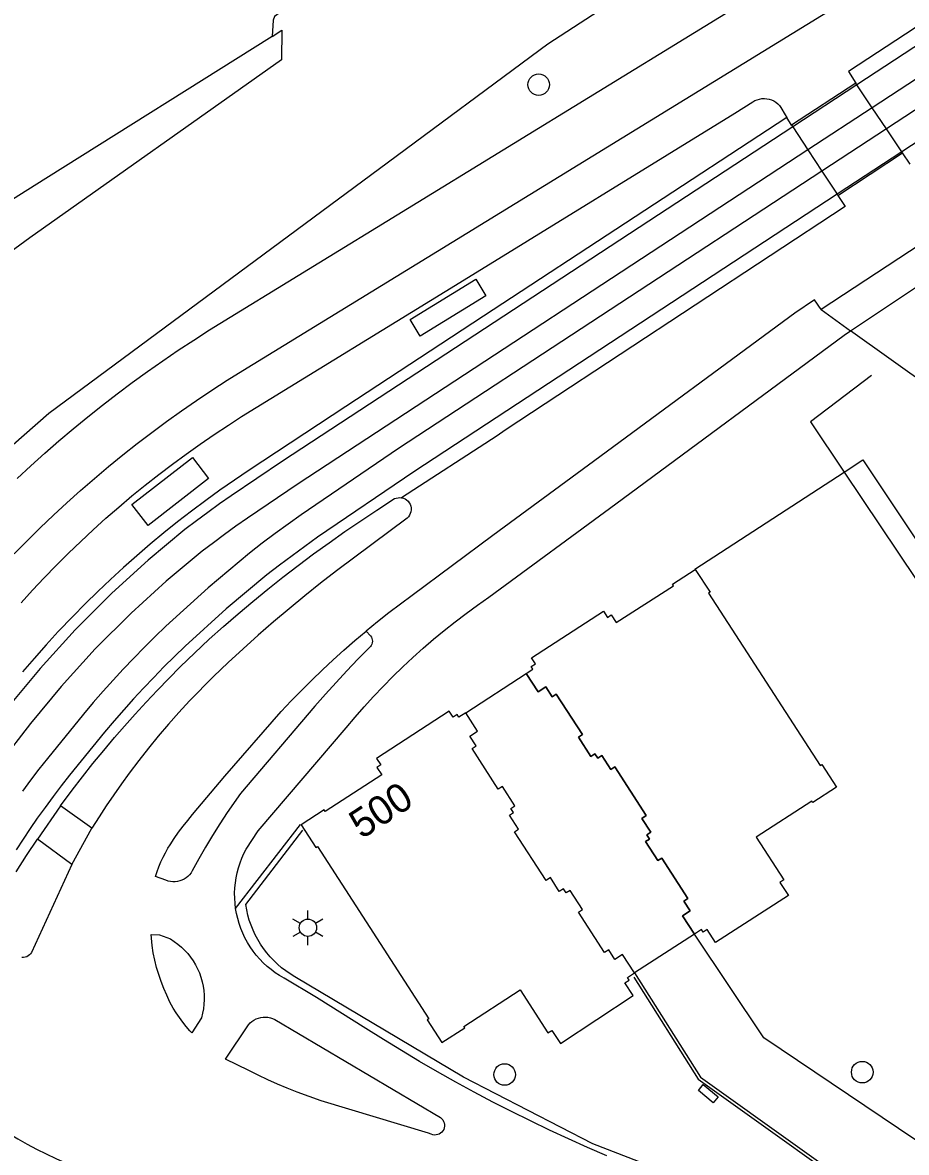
# Model space of a CAD drawing. Extents: x 122462 to 123306, y 485548 to 486417.
# Drawn here: x 123112.8 to 123158.7, y 486289.8 to 486348.4 of the extents above; entities that cross this region are included whole.
import ezdxf

# ---------------------------------------------------------------- set-up
doc = ezdxf.new("R2010")
doc.units = 0
for name, color, linetype in [('Level 1', 7, 'Continuous'), ('Level 10', 7, 'Continuous'), ('Level 16', 7, 'Continuous'), ('Level 17', 7, 'Continuous'), ('Level 19', 7, 'Continuous'), ('Level 2', 7, 'Continuous'), ('Level 20', 7, 'Continuous'), ('Level 24', 7, 'Continuous'), ('Level 25', 7, 'Continuous'), ('Level 37', 7, 'Continuous'), ('Level 40', 7, 'Continuous'), ('Level 44', 7, 'Continuous'), ('Level 50', 7, 'Continuous'), ('Level 53', 7, 'Continuous'), ('Level 58', 7, 'Continuous')]:
    doc.layers.add(name, color=color, linetype=linetype)

msp = doc.modelspace()

# ---------------------------------------------------------------- linework, layer by layer
at = {"layer": 'Level 1'}
for points in [[(123144.558, 486299.075), (123143.943, 486300.024), (123143.549, 486299.768), (123143.222, 486300.271), (123143.012, 486300.134), (123141.653, 486302.233), (123141.859, 486302.367), (123141.216, 486303.356), (123141.012, 486303.224), (123140.87, 486303.443), (123140.659, 486303.306), (123140.195, 486304.019), (123139.968, 486303.872), (123138.332, 486306.399), (123138.541, 486306.535), (123138.073, 486307.256), (123138.282, 486307.392), (123138.14, 486307.61), (123138.349, 486307.745), (123137.702, 486308.745), (123137.492, 486308.609), (123136.128, 486310.716), (123136.339, 486310.852), (123136.008, 486311.364), (123136.41, 486311.624), (123135.798, 486312.574), (123135.445, 486312.346), (123135.358, 486312.48), (123135.148, 486312.344), (123134.946, 486312.655), (123131.169, 486310.21), (123131.388, 486309.873), (123131.187, 486309.743), (123131.441, 486309.353), (123128.503, 486307.452), (123128.449, 486307.536), (123127.25, 486306.76)], [(123127.25, 486306.76), (123128.016, 486305.577), (123128.1, 486305.631), (123133.882, 486296.692), (123133.8, 486296.639), (123134.566, 486295.455), (123135.749, 486296.219), (123135.697, 486296.299), (123138.625, 486298.193), (123140.07, 486295.959), (123140.277, 486296.094), (123140.719, 486295.41), (123144.499, 486297.9), (123144.068, 486298.566), (123144.283, 486298.706), (123144.195, 486298.84), (123144.558, 486299.075)]]:
    msp.add_lwpolyline(points, dxfattribs=at)
at = {"layer": 'Level 10'}
msp.add_lwpolyline([(123144.558, 486299.075), (123143.943, 486300.024), (123143.549, 486299.768), (123143.222, 486300.271), (123143.012, 486300.134), (123141.653, 486302.233), (123141.859, 486302.367), (123141.216, 486303.356), (123141.012, 486303.224), (123140.87, 486303.443), (123140.659, 486303.306), (123140.195, 486304.019), (123139.968, 486303.872), (123138.332, 486306.399), (123138.541, 486306.535), (123138.073, 486307.256), (123138.282, 486307.392), (123138.14, 486307.61), (123138.349, 486307.745), (123137.702, 486308.745), (123137.492, 486308.609), (123136.128, 486310.716), (123136.339, 486310.852), (123136.008, 486311.364), (123136.41, 486311.624), (123135.798, 486312.574), (123138.94, 486314.608), (123139.556, 486313.66), (123139.958, 486313.921), (123140.289, 486313.409), (123140.5, 486313.546), (123141.864, 486311.439), (123141.654, 486311.303), (123142.301, 486310.304), (123142.51, 486310.439), (123142.651, 486310.22), (123142.86, 486310.355), (123143.327, 486309.633), (123143.536, 486309.768), (123145.172, 486307.241), (123144.945, 486307.094), (123145.406, 486306.379), (123145.195, 486306.243), (123145.336, 486306.024), (123145.132, 486305.892), (123145.772, 486304.9), (123145.978, 486305.033), (123147.337, 486302.934), (123147.126, 486302.798), (123147.451, 486302.294), (123147.056, 486302.039), (123147.67, 486301.09), (123144.558, 486299.075)], dxfattribs=at)
at = {"layer": 'Level 16'}
for points in [[(123217.361, 486416.958), (123206.829, 486406.748), (123179.003, 486385.844), (123152.655, 486367.889), (123137.927, 486357.79), (123128.826, 486350.852), (123125.877, 486348.714), (123125.807, 486348.517), (123125.744, 486347.678)], [(123125.744, 486347.678), (123114.003, 486340.298), (123094.86, 486328.266)]]:
    msp.add_lwpolyline(points, dxfattribs=at)
at = {"layer": 'Level 17'}
for p, q in [((123156.044, 486345.251), (123152.716, 486343.072)), ((123156.102, 486345.165), (123156.044, 486345.251)), ((123156.905, 486343.969), (123156.102, 486345.165)), ((123157.637, 486342.879), (123156.905, 486343.969)), ((123152.716, 486343.072), (123152.472, 486343.461)), ((123152.716, 486343.072), (123152.773, 486342.985)), ((123152.773, 486342.985), (123153.567, 486341.783)), ((123168.085, 486342.615), (123154.252, 486333.498)), ((123158.44, 486341.683), (123157.637, 486342.879)), ((123153.567, 486341.783), (123154.291, 486340.687)), ((123155.123, 486339.427), (123158.471, 486341.637)), ((123158.471, 486341.637), (123158.44, 486341.683)), ((123154.291, 486340.687), (123155.085, 486339.485)), ((123155.085, 486339.485), (123155.123, 486339.427)), ((123154.252, 486333.498), (123155.775, 486332.404)), ((123160.559, 486328.969), (123155.775, 486332.404)), ((123114.765, 486307.744), (123113.564, 486306.012)), ((123116.4, 486306.588), (123114.765, 486307.744)), ((123115.361, 486304.695), (123116.4, 486306.588)), ((123115.361, 486304.695), (123113.564, 486306.012))]:
    msp.add_line(p, q, dxfattribs=at)
for points in [[(123112.519, 486324.734), (123113.232, 486325.395), (123113.954, 486326.046), (123114.686, 486326.685), (123115.428, 486327.313), (123116.179, 486327.93), (123116.939, 486328.536), (123117.709, 486329.129), (123118.487, 486329.712), (123119.274, 486330.282), (123120.07, 486330.84), (123120.874, 486331.386), (123121.687, 486331.92), (123122.507, 486332.441), (123132.782, 486338.745), (123187.402, 486372.258)], [(123112.364, 486320.819), (123113.031, 486321.499), (123113.71, 486322.169), (123114.398, 486322.828), (123115.097, 486323.476), (123115.807, 486324.113), (123116.526, 486324.738), (123117.255, 486325.352), (123117.994, 486325.954), (123118.742, 486326.544), (123119.5, 486327.123), (123120.266, 486327.689), (123121.042, 486328.243), (123121.826, 486328.785), (123122.619, 486329.314), (123123.42, 486329.83), (123124.229, 486330.334), (123134.337, 486336.539), (123186.289, 486368.432)], [(123182.901, 486363.701), (123155.674, 486345.856), (123156.044, 486345.251)], [(123112.72, 486318.277), (123113.317, 486318.936), (123113.925, 486319.584), (123114.544, 486320.223), (123115.174, 486320.85), (123115.814, 486321.468), (123116.464, 486322.074), (123117.125, 486322.669), (123117.795, 486323.253), (123118.475, 486323.826), (123119.165, 486324.387), (123119.864, 486324.936), (123120.573, 486325.473), (123121.29, 486325.999), (123122.016, 486326.512), (123122.75, 486327.013), (123123.493, 486327.502), (123124.166, 486327.947), (123135.489, 486334.905), (123149.775, 486343.685), (123150.697, 486344.279), (123150.808, 486344.342), (123150.925, 486344.392), (123151.048, 486344.427), (123151.174, 486344.448), (123151.302, 486344.453), (123151.429, 486344.443), (123151.554, 486344.418), (123151.675, 486344.378), (123151.791, 486344.324), (123151.899, 486344.256), (123151.998, 486344.176), (123152.087, 486344.084), (123152.165, 486343.983), (123152.384, 486343.601), (123152.472, 486343.461)], [(123152.472, 486343.461), (123136.722, 486333.156), (123129.568, 486328.475), (123124.558, 486325.164), (123123.797, 486324.653), (123123.044, 486324.129), (123122.301, 486323.592), (123121.566, 486323.043), (123120.841, 486322.482), (123120.125, 486321.909), (123119.419, 486321.324), (123118.723, 486320.727), (123118.037, 486320.119), (123117.362, 486319.499), (123116.696, 486318.868), (123116.042, 486318.226), (123115.398, 486317.573), (123114.65, 486316.786), (123114.02, 486316.098), (123113.402, 486315.4), (123112.796, 486314.692)], [(123158.867, 486341.039), (123158.471, 486341.637)], [(123155.775, 486332.404), (123163.868, 486337.789), (123167.35, 486340.065)], [(123155.123, 486339.427), (123155.505, 486338.853), (123139.924, 486328.615), (123137.845, 486327.249), (123137.432, 486326.952), (123132.468, 486323.738)], [(123154.252, 486333.498), (123153.901, 486334.011), (123152.891, 486333.312), (123142.169, 486325.432), (123137.2, 486321.78), (123133.014, 486318.656), (123132.407, 486318.21), (123131.808, 486317.754), (123131.216, 486317.289), (123130.632, 486316.813)], [(123123.856, 486302.418), (123123.805, 486303.221), (123123.817, 486303.486), (123123.843, 486303.75), (123123.883, 486304.012), (123123.937, 486304.271), (123124.005, 486304.527), (123124.086, 486304.78), (123124.181, 486305.027), (123124.289, 486305.269), (123124.41, 486305.505), (123125.019, 486306.446), (123129.594, 486311.79), (123130.055, 486312.342), (123130.528, 486312.884), (123131.012, 486313.417), (123131.506, 486313.939), (123132.011, 486314.451), (123132.527, 486314.953), (123133.052, 486315.444), (123133.588, 486315.924), (123134.133, 486316.393), (123134.688, 486316.851), (123135.252, 486317.297), (123135.825, 486317.732), (123136.407, 486318.155), (123136.997, 486318.566), (123143.584, 486323.424), (123155.453, 486332.176), (123155.775, 486332.404)], [(123155.439, 486325.068), (123156.41, 486325.7), (123182.857, 486286.063), (123184.719, 486283.363), (123187.267, 486285.039), (123187.906, 486284.133)], [(123147.715, 486320.009), (123147.7, 486320.033), (123155.439, 486325.068)], [(123114.765, 486307.744), (123115.372, 486308.557), (123115.907, 486309.251), (123116.451, 486309.937), (123117.006, 486310.615), (123117.57, 486311.285), (123118.079, 486311.873), (123118.643, 486312.507), (123119.215, 486313.133), (123119.796, 486313.751), (123120.385, 486314.362), (123120.982, 486314.964), (123122.484, 486316.389), (123123.229, 486317.055), (123123.983, 486317.711), (123124.747, 486318.355), (123125.521, 486318.987), (123126.304, 486319.608), (123127.096, 486320.218), (123127.897, 486320.815), (123128.707, 486321.401), (123129.526, 486321.974), (123130.353, 486322.535), (123131.188, 486323.084), (123132.107, 486323.69), (123132.377, 486323.747), (123132.468, 486323.738)], [(123132.468, 486323.738), (123132.562, 486323.714), (123132.652, 486323.674), (123132.734, 486323.621), (123132.806, 486323.555), (123132.866, 486323.478), (123132.913, 486323.393), (123132.946, 486323.301), (123132.964, 486323.205), (123132.966, 486323.108), (123132.953, 486323.011), (123132.923, 486322.918), (123132.88, 486322.831), (123132.822, 486322.752), (123132.753, 486322.683), (123129.1, 486319.946), (123128.266, 486319.301), (123127.442, 486318.643), (123126.627, 486317.974), (123125.821, 486317.293), (123125.026, 486316.601), (123124.24, 486315.898), (123123.465, 486315.183), (123122.7, 486314.457), (123121.457, 486313.188), (123120.906, 486312.591), (123120.367, 486311.982), (123119.84, 486311.364), (123119.326, 486310.735), (123118.823, 486310.097), (123118.328, 486309.441), (123117.923, 486308.884), (123117.528, 486308.319), (123117.142, 486307.749), (123116.766, 486307.171), (123116.4, 486306.588)], [(123130.632, 486316.813), (123130.861, 486316.561), (123130.901, 486316.499), (123130.931, 486316.43), (123130.948, 486316.358), (123130.953, 486316.284), (123130.946, 486316.21), (123130.926, 486316.138), (123130.894, 486316.071), (123130.852, 486316.01), (123130.207, 486315.356), (123129.635, 486314.759), (123129.072, 486314.154), (123128.519, 486313.54), (123127.975, 486312.918), (123124.11, 486308.384), (123123.419, 486307.402), (123123.03, 486306.811), (123122.654, 486306.212), (123122.291, 486305.605), (123121.941, 486304.99), (123121.605, 486304.368), (123121.541, 486304.264), (123121.465, 486304.169), (123121.379, 486304.082), (123121.284, 486304.006), (123121.181, 486303.94), (123121.071, 486303.887), (123120.956, 486303.846), (123120.838, 486303.819), (123120.716, 486303.804), (123120.595, 486303.804), (123120.473, 486303.817), (123120.354, 486303.844), (123120.239, 486303.884), (123119.696, 486304.071), (123119.778, 486304.332), (123119.87, 486304.584), (123119.973, 486304.832), (123120.086, 486305.075), (123120.209, 486305.313), (123120.343, 486305.546), (123120.454, 486305.723), (123120.67, 486306.05), (123120.895, 486306.371), (123121.129, 486306.685), (123121.373, 486306.991), (123121.625, 486307.291), (123123.295, 486309.29), (123126.226, 486312.641), (123126.746, 486313.194), (123127.275, 486313.739), (123127.813, 486314.274), (123128.359, 486314.801), (123128.915, 486315.318), (123129.479, 486315.826), (123130.051, 486316.325), (123130.632, 486316.813)], [(123123.856, 486302.418), (123127.215, 486306.778), (123127.25, 486306.76)], [(123112.461, 486304.316), (123113.006, 486305.168), (123113.564, 486306.012)], [(123115.361, 486304.695), (123113.255, 486300.139), (123113.21, 486300.068), (123113.153, 486300.006), (123113.087, 486299.955), (123113.013, 486299.915), (123112.933, 486299.888), (123112.85, 486299.876), (123112.766, 486299.877)], [(123143.13, 486289.587), (123142.129, 486290.019), (123141.133, 486290.464), (123140.144, 486290.922), (123139.16, 486291.393), (123138.183, 486291.876), (123137.212, 486292.373), (123136.247, 486292.882), (123135.289, 486293.403), (123134.338, 486293.937), (123133.395, 486294.483), (123132.458, 486295.042), (123131.529, 486295.612), (123130.607, 486296.195), (123128.062, 486297.796), (123126.367, 486298.801), (123126.135, 486298.937), (123125.911, 486299.084), (123125.696, 486299.244), (123125.489, 486299.416), (123125.292, 486299.598), (123125.105, 486299.791), (123124.929, 486299.993), (123124.764, 486300.205), (123124.611, 486300.426), (123124.47, 486300.654), (123124.342, 486300.89), (123124.227, 486301.132), (123124.125, 486301.381), (123124.037, 486301.634), (123123.962, 486301.892), (123123.902, 486302.154), (123123.856, 486302.418)], [(123121.591, 486295.959), (123121.486, 486296.072), (123121.293, 486296.293), (123121.109, 486296.522), (123120.934, 486296.757), (123120.768, 486297), (123120.611, 486297.248), (123120.445, 486297.565), (123120.279, 486297.913), (123120.127, 486298.268), (123119.989, 486298.628), (123119.866, 486298.994), (123119.756, 486299.364), (123119.661, 486299.737), (123119.581, 486300.115), (123119.516, 486300.495), (123119.479, 486301.069), (123119.912, 486301.047), (123120.467, 486300.839), (123120.667, 486300.712), (123120.857, 486300.572), (123121.038, 486300.419), (123121.209, 486300.255), (123121.368, 486300.081), (123121.516, 486299.895), (123121.651, 486299.701), (123121.773, 486299.498), (123121.881, 486299.288), (123121.975, 486299.071), (123122.054, 486298.848), (123122.119, 486298.62), (123122.168, 486298.389), (123122.203, 486298.154), (123122.221, 486297.919), (123122.224, 486297.682), (123122.211, 486297.446), (123122.183, 486297.211), (123122.139, 486296.978), (123122.08, 486296.749), (123121.591, 486295.959)], [(123167.048, 486285.085), (123151.278, 486295.704), (123147.67, 486301.09)], [(123144.558, 486299.075), (123147.98, 486293.667), (123158.171, 486286.382), (123157.557, 486284.767)], [(123134.179, 486290.662), (123134.094, 486290.673), (123134.013, 486290.699), (123133.861, 486290.752), (123128.293, 486292.434), (123127.049, 486292.882), (123126.537, 486293.086), (123126.03, 486293.302), (123125.528, 486293.527), (123125.03, 486293.764), (123124.538, 486294.011), (123123.338, 486294.593), (123124.519, 486296.388), (123124.605, 486296.48), (123124.702, 486296.561), (123124.806, 486296.631), (123124.918, 486296.688), (123125.036, 486296.733), (123125.158, 486296.764), (123125.283, 486296.781), (123125.409, 486296.784), (123125.534, 486296.773), (123125.658, 486296.747), (123125.777, 486296.708), (123125.892, 486296.656), (123134.491, 486291.564), (123134.556, 486291.509), (123134.611, 486291.443), (123134.653, 486291.37), (123134.683, 486291.29), (123134.698, 486291.206), (123134.699, 486291.121), (123134.685, 486291.037), (123134.657, 486290.956), (123134.616, 486290.882), (123134.563, 486290.815), (123134.499, 486290.759), (123134.426, 486290.714), (123134.347, 486290.683), (123134.264, 486290.665), (123134.179, 486290.662)]]:
    msp.add_lwpolyline(points, dxfattribs=at)
at = {"layer": 'Level 19'}
for points in [[(123125.744, 486347.678), (123126.256, 486348), (123126.229, 486346.453), (123113.173, 486337.214), (123109.074, 486334.233), (123099.823, 486327.302)], [(123131.328, 486340.807), (123114.161, 486328.11), (123109.594, 486324.103)]]:
    msp.add_lwpolyline(points, dxfattribs=at)
at = {"layer": 'Level 2'}
for points in [[(123147.67, 486301.09), (123147.056, 486302.039), (123147.451, 486302.294), (123147.126, 486302.798), (123147.337, 486302.934), (123145.978, 486305.033), (123145.772, 486304.9), (123145.132, 486305.892), (123145.336, 486306.024), (123145.195, 486306.243), (123145.406, 486306.379), (123144.945, 486307.094), (123145.172, 486307.241), (123143.536, 486309.768), (123143.327, 486309.633), (123142.86, 486310.355), (123142.651, 486310.22), (123142.51, 486310.439), (123142.301, 486310.304), (123141.654, 486311.303), (123141.864, 486311.439), (123140.5, 486313.546), (123140.289, 486313.409), (123139.958, 486313.921), (123139.556, 486313.66), (123138.94, 486314.608), (123139.292, 486314.837), (123139.205, 486314.971), (123139.415, 486315.107), (123139.213, 486315.42), (123142.949, 486317.843), (123143.154, 486317.526), (123143.355, 486317.656), (123143.61, 486317.261), (123146.588, 486319.159), (123146.533, 486319.242), (123147.715, 486320.009)], [(123147.715, 486320.009), (123148.482, 486318.828), (123148.399, 486318.774), (123154.2, 486309.841), (123154.283, 486309.895), (123155.049, 486308.716), (123153.81, 486307.912), (123153.759, 486307.992), (123150.876, 486306.12), (123152.319, 486303.897), (123152.112, 486303.763), (123152.559, 486303.09), (123148.759, 486300.66), (123148.33, 486301.325), (123148.12, 486301.189), (123148.033, 486301.325), (123147.67, 486301.09)]]:
    msp.add_lwpolyline(points, dxfattribs=at)
at = {"layer": 'Level 20'}
msp.add_lwpolyline([(123227.128, 486416.958), (123226.347, 486416.118), (123214.358, 486404.642), (123207.4, 486399.966), (123200.277, 486394.449), (123191.597, 486386.324), (123182.341, 486378.222), (123175.379, 486372.758), (123164.712, 486365.388), (123158.016, 486360.276), (123153.237, 486354.953), (123145.688, 486350.946), (123140.068, 486347.272), (123131.328, 486340.807)], dxfattribs=at)
at = {"layer": 'Level 24'}
for points in [[(123148.741, 486287.743), (123142.401, 486290.204), (123135.682, 486293.672), (123126.922, 486298.879), (123126.687, 486299.023), (123126.461, 486299.178), (123126.243, 486299.346), (123126.034, 486299.525), (123125.835, 486299.715), (123125.646, 486299.915), (123125.468, 486300.125), (123125.302, 486300.344), (123125.147, 486300.571), (123125.005, 486300.807), (123124.876, 486301.049), (123124.759, 486301.298), (123124.656, 486301.553), (123124.567, 486301.813), (123124.491, 486302.078), (123124.43, 486302.346), (123124.383, 486302.617), (123127.352, 486306.488)], [(123144.52, 486298.857), (123147.87, 486293.563), (123157.99, 486286.329)]]:
    msp.add_lwpolyline(points, dxfattribs=at)
at = {"layer": 'Level 25'}
for points in [[(123156.866, 486330.077), (123153.693, 486327.67), (123155.439, 486325.068)], [(123155.439, 486325.068), (123184.422, 486281.872), (123187.906, 486284.133)]]:
    msp.add_lwpolyline(points, dxfattribs=at)
at = {"layer": 'Level 37'}
for p, q in [((123156.102, 486345.165), (123152.773, 486342.985)), ((123156.905, 486343.969), (123153.567, 486341.783)), ((123157.637, 486342.879), (123154.291, 486340.687)), ((123158.44, 486341.683), (123155.085, 486339.485))]:
    msp.add_line(p, q, dxfattribs=at)
for points in [[(123241.03, 486411.185), (123231.744, 486401.974), (123225.952, 486396.381), (123222.721, 486393.366), (123219.946, 486390.881), (123216.94, 486388.248), (123213.765, 486385.527), (123210.569, 486382.869), (123207.368, 486380.288), (123204.076, 486377.707), (123200.759, 486375.175), (123197.416, 486372.695), (123193.966, 486370.217), (123190.616, 486367.88), (123184.983, 486364.082), (123156.102, 486345.165)], [(123242.034, 486410.153), (123232.751, 486400.945), (123226.939, 486395.332), (123223.692, 486392.302), (123220.904, 486389.806), (123217.883, 486387.161), (123214.693, 486384.426), (123211.482, 486381.755), (123208.265, 486379.161), (123204.957, 486376.568), (123201.624, 486374.024), (123198.265, 486371.533), (123194.8, 486369.043), (123191.437, 486366.696), (123185.777, 486362.88), (123156.905, 486343.969)], [(123242.948, 486409.215), (123233.663, 486400.005), (123227.574, 486394.133), (123224.193, 486390.984), (123221.287, 486388.391), (123218.124, 486385.639), (123214.783, 486382.796), (123211.462, 486380.052), (123208.135, 486377.388), (123204.717, 486374.728), (123201.271, 486372.12), (123198.042, 486369.744), (123194.714, 486367.37), (123191.238, 486364.965), (123186.373, 486361.706), (123157.637, 486342.879)], [(123243.952, 486408.183), (123234.67, 486398.976), (123228.56, 486393.083), (123225.163, 486389.918), (123222.242, 486387.313), (123219.064, 486384.548), (123215.707, 486381.691), (123212.37, 486378.935), (123209.028, 486376.258), (123205.594, 486373.586), (123202.132, 486370.966), (123198.888, 486368.578), (123195.543, 486366.192), (123192.054, 486363.778), (123187.166, 486360.503), (123158.44, 486341.683)], [(123152.773, 486342.985), (123126.291, 486325.639), (123123.626, 486323.837), (123123.017, 486323.411), (123122.414, 486322.977), (123121.817, 486322.534), (123121.226, 486322.084), (123119.316, 486320.5), (123117.434, 486318.788), (123115.525, 486316.887), (123113.71, 486314.876), (123112.068, 486312.907), (123111.653, 486312.393), (123111.246, 486311.872), (123110.846, 486311.346), (123110.455, 486310.813), (123110.096, 486310.298), (123109.745, 486309.776), (123109.403, 486309.249), (123109.07, 486308.716), (123108.747, 486308.177), (123106.961, 486305.004), (123106.073, 486303.344)], [(123153.567, 486341.783), (123127.103, 486324.449), (123124.469, 486322.668), (123123.874, 486322.252), (123123.285, 486321.828), (123122.701, 486321.396), (123122.124, 486320.955), (123120.256, 486319.407), (123118.425, 486317.741), (123116.568, 486315.891), (123114.802, 486313.935), (123113.204, 486312.019), (123111.633, 486309.979), (123111.283, 486309.477), (123110.941, 486308.97), (123110.609, 486308.456), (123110.285, 486307.937), (123109.97, 486307.413), (123108.209, 486304.285), (123107.338, 486302.661), (123104.553, 486296.801)], [(123154.291, 486340.687), (123132.309, 486326.284), (123127.262, 486322.847), (123126.582, 486322.364), (123125.908, 486321.872), (123125.24, 486321.372), (123124.579, 486320.863), (123122.422, 486319.066), (123120.233, 486317.066), (123119.67, 486316.522), (123119.114, 486315.97), (123118.565, 486315.41), (123118.025, 486314.843), (123117.496, 486314.269), (123116.975, 486313.688), (123116.461, 486313.1), (123115.955, 486312.505), (123114.086, 486310.207), (123113.644, 486309.646), (123113.21, 486309.078), (123112.785, 486308.504)], [(123155.085, 486339.485), (123133.109, 486325.087), (123128.111, 486321.683), (123127.444, 486321.21), (123126.784, 486320.728), (123126.13, 486320.237), (123125.482, 486319.738), (123123.366, 486317.976), (123121.23, 486316.024), (123120.68, 486315.493), (123120.137, 486314.955), (123119.602, 486314.409), (123119.075, 486313.855), (123118.559, 486313.295), (123118.05, 486312.728), (123117.549, 486312.154), (123117.055, 486311.574), (123115.231, 486309.33), (123114.8, 486308.782), (123114.376, 486308.228), (123113.961, 486307.667), (123113.554, 486307.101), (123113.183, 486306.561), (123112.822, 486306.015), (123112.47, 486305.463)], [(123106.826, 486294.73), (123107.185, 486294.422), (123107.815, 486293.892), (123108.453, 486293.371), (123109.097, 486292.858), (123109.748, 486292.353), (123110.199, 486292.011), (123110.658, 486291.679), (123111.123, 486291.357), (123111.596, 486291.045), (123112.075, 486290.743), (123112.553, 486290.463), (123113.037, 486290.193), (123113.527, 486289.934), (123114.022, 486289.686), (123114.523, 486289.448), (123115.028, 486289.221), (123115.906, 486288.844), (123116.789, 486288.478), (123117.677, 486288.123), (123118.568, 486287.779), (123120.424, 486287.086), (123126.082, 486285.333)]]:
    msp.add_lwpolyline(points, dxfattribs=at)
at = {"layer": 'Level 40'}
msp.add_lwpolyline([(123148.65, 486292.338), (123147.879, 486292.975), (123148.134, 486293.284), (123148.905, 486292.647), (123148.65, 486292.338)], dxfattribs=at)
at = {"layer": 'Level 44'}
for points in [[(123133.441, 486332.124), (123132.914, 486332.985), (123136.325, 486335.072), (123136.852, 486334.211), (123133.441, 486332.124)], [(123119.31, 486322.297), (123118.466, 486323.381), (123121.609, 486325.824), (123122.453, 486324.74), (123119.31, 486322.297)]]:
    msp.add_lwpolyline(points, dxfattribs=at)
at = {"layer": 'Level 50'}
for p, q in [((123127.608, 486301.872), (123127.608, 486302.322)), ((123127.218, 486301.647), (123126.828, 486301.872)), ((123128.387, 486301.872), (123127.997, 486301.647)), ((123127.218, 486301.197), (123126.828, 486300.972)), ((123127.608, 486300.522), (123127.608, 486300.972)), ((123128.387, 486300.972), (123127.997, 486301.197))]:
    msp.add_line(p, q, dxfattribs=at)
msp.add_circle((123127.608, 486301.422), 0.45, dxfattribs=at)
at = {"layer": 'Level 53'}
for centre in [(123139.587, 486345.172), (123156.383, 486293.924), (123137.819, 486293.801)]:
    msp.add_circle(centre, 0.56, dxfattribs=at)

# ---------------------------------------------------------------- texts
at = {"layer": 'Level 58'}
msp.add_text('500', height=1.5, rotation=33.18161, dxfattribs=at).set_placement((123130.397, 486305.987))

doc.saveas('drawing.dxf')
